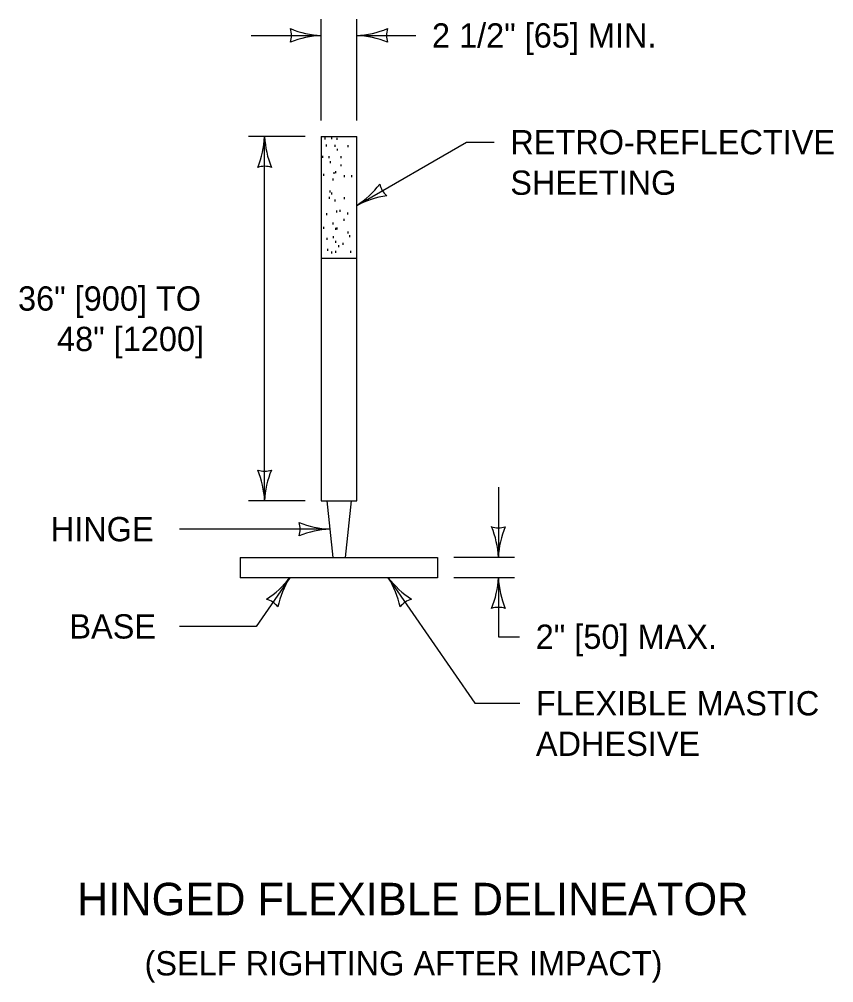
# Model space of a CAD drawing. Extents: x 49991.4 to 50024.6, y 49987.6 to 50011.4.
# Drawn here: x 50022.61 to 50024.622, y 49990.008 to 49992.389 of the extents above; entities that cross this region are included whole.
import ezdxf

# ---------------------------------------------------------------- set-up
doc = ezdxf.new("R2010")
doc.units = 0
for name, color, linetype in [('Level 1', 7, 'Continuous'), ('Level 2', 7, 'Continuous'), ('Level 3', 7, 'Continuous')]:
    doc.layers.add(name, color=color, linetype=linetype)

msp = doc.modelspace()

# ---------------------------------------------------------------- linework, layer by layer
at = {"layer": 'Level 1'}
for p, q in [((50023.356, 49992.0992), (50023.356, 49991.1992)), ((50023.356, 49992.0992), (50023.4435, 49992.0992)), ((50023.3656, 49992.0921), (50023.3656, 49992.097)), ((50023.3824, 49992.093), (50023.3824, 49992.0979)), ((50023.3949, 49992.0914), (50023.3949, 49992.0963)), ((50023.4435, 49991.1992), (50023.4435, 49992.0992)), ((50023.3691, 49992.0751), (50023.3691, 49992.08)), ((50023.3901, 49992.0738), (50023.3901, 49992.0786)), ((50023.396, 49992.0645), (50023.396, 49992.0694)), ((50023.4225, 49992.0734), (50023.4225, 49992.0782)), ((50023.3602, 49992.0466), (50023.3602, 49992.0515)), ((50023.3758, 49992.0461), (50023.3758, 49992.051)), ((50023.3786, 49992.0338), (50023.3786, 49992.0386)), ((50023.4049, 49992.0462), (50023.4049, 49992.0511)), ((50023.4049, 49992.0259), (50023.4049, 49992.0307)), ((50023.3622, 49992.0025), (50023.3622, 49992.0074)), ((50023.3854, 49991.9904), (50023.3854, 49991.9953)), ((50023.3879, 49992.0069), (50023.3879, 49992.0117)), ((50023.3921, 49992.0086), (50023.3921, 49992.0135)), ((50023.413, 49991.9987), (50023.413, 49992.0036)), ((50023.4313, 49991.9994), (50023.4313, 49992.0042)), ((50023.3759, 49991.9455), (50023.3759, 49991.9504)), ((50023.3778, 49991.9614), (50023.3778, 49991.9662)), ((50023.382, 49991.9564), (50023.382, 49991.9613)), ((50023.3901, 49991.9388), (50023.3901, 49991.9436)), ((50023.413, 49991.9444), (50023.413, 49991.9492)), ((50023.3697, 49991.9049), (50023.3697, 49991.9098)), ((50023.3946, 49991.9119), (50023.3946, 49991.9167)), ((50023.403, 49991.913), (50023.403, 49991.9179)), ((50023.4123, 49991.8909), (50023.4123, 49991.8957)), ((50023.4218, 49991.9071), (50023.4218, 49991.912)), ((50023.3622, 49991.871), (50023.3622, 49991.8759)), ((50023.3854, 49991.8818), (50023.3854, 49991.8866)), ((50023.3921, 49991.8689), (50023.3921, 49991.8738)), ((50023.3954, 49991.8699), (50023.3954, 49991.8747)), ((50023.3704, 49991.8445), (50023.3704, 49991.8494)), ((50023.3859, 49991.8481), (50023.3859, 49991.853)), ((50023.4225, 49991.8596), (50023.4225, 49991.8645)), ((50023.4265, 49991.8509), (50023.4265, 49991.8557)), ((50023.3921, 49991.837), (50023.3921, 49991.8419)), ((50023.3994, 49991.8257), (50023.3994, 49991.8306)), ((50023.4103, 49991.8319), (50023.4103, 49991.8367)), ((50023.3725, 49991.8166), (50023.3725, 49991.8215)), ((50023.3824, 49991.8101), (50023.3824, 49991.815)), ((50023.3921, 49991.8119), (50023.3921, 49991.8168)), ((50023.4293, 49991.8121), (50023.4293, 49991.817)), ((50023.356, 49991.7992), (50023.4435, 49991.7992)), ((50023.356, 49991.1992), (50023.4435, 49991.1992)), ((50023.3697, 49991.1992), (50023.3847, 49991.0593)), ((50023.4297, 49991.1992), (50023.4147, 49991.0593)), ((50023.156, 49991.0593), (50023.156, 49991.0093)), ((50023.156, 49991.0593), (50023.6435, 49991.0593)), ((50023.6435, 49991.0593), (50023.6435, 49991.0093)), ((50023.6435, 49991.0093), (50023.156, 49991.0093))]:
    msp.add_line(p, q, dxfattribs=at)
at = {"layer": 'Level 3'}
for p, q in [((50023.356, 49992.1392), (50023.356, 49992.3892)), ((50023.4435, 49992.1392), (50023.4435, 49992.3892)), ((50023.1825, 49992.3492), (50023.356, 49992.3492)), ((50023.4435, 49992.3492), (50023.5894, 49992.3492)), ((50023.316, 49992.0992), (50023.176, 49992.0992)), ((50023.216, 49991.1992), (50023.216, 49992.0992)), ((50023.7935, 49991.2327), (50023.7935, 49991.0593)), ((50023.316, 49991.1992), (50023.176, 49991.1992)), ((50023.3772, 49991.1292), (50023.006, 49991.1292)), ((50023.8335, 49991.0593), (50023.6835, 49991.0593)), ((50023.8335, 49991.0093), (50023.6835, 49991.0093)), ((50023.7351, 49990.6989), (50023.8462, 49990.6989))]:
    msp.add_line(p, q, dxfattribs=at)
for points in [[(50023.4435, 49991.9288), (50023.7148, 49992.0854), (50023.783, 49992.0854)], [(50023.2779, 49991.0093), (50023.1951, 49990.8889), (50023.006, 49990.8889)], [(50023.5216, 49991.0093), (50023.7351, 49990.6989), (50023.8462, 49990.6989)], [(50023.7935, 49991.0093), (50023.7935, 49990.8634), (50023.8457, 49990.8634)]]:
    msp.add_lwpolyline(points, dxfattribs=at)
for centre, radius, start, end in [((50023.3651, 49992.5713), 0.2223, 247.456, 267.6395), ((50023.2278, 49992.3492), 0.0548, 342.1388, 17.8612), ((50023.3675, 49992.1165), 0.233, 92.8273, 112.0772), ((50023.432, 49992.5819), 0.233, 272.8273, 292.0772), ((50023.4343, 49992.127), 0.2223, 67.456, 87.6395), ((50023.5717, 49992.3492), 0.0548, 162.1388, 197.8612), ((50022.9938, 49992.1083), 0.2223, 337.456, 357.6395), ((50023.4487, 49992.1107), 0.233, 182.8273, 202.0772), ((50023.216, 49991.971), 0.0548, 72.1388, 107.8612), ((50023.3156, 49992.1236), 0.233, 303.2811, 322.5309), ((50023.554, 49991.9938), 0.0548, 192.5926, 228.3149), ((50023.5482, 49991.7327), 0.2223, 97.9098, 118.0933), ((50023.216, 49991.3274), 0.0548, 252.1388, 287.8612), ((50022.9833, 49991.1877), 0.233, 2.8273, 22.0772), ((50023.4381, 49991.19), 0.2223, 157.456, 177.6395), ((50023.3863, 49991.3513), 0.2223, 247.456, 267.6395), ((50023.249, 49991.1292), 0.0548, 342.1388, 17.8612), ((50023.7935, 49991.1875), 0.0548, 252.1388, 287.8612), ((50023.5608, 49991.0478), 0.233, 2.8273, 22.0772), ((50024.0156, 49991.0501), 0.2223, 157.456, 177.6395), ((50023.3887, 49990.8965), 0.233, 92.8273, 112.0772), ((50023.1, 49991.1427), 0.2223, 302.9394, 323.1229), ((50023.4761, 49990.8869), 0.233, 148.3107, 167.5606), ((50023.3334, 49990.8909), 0.2223, 11.9771, 32.1606), ((50023.7068, 49991.1506), 0.233, 217.3484, 236.5982), ((50023.5713, 49991.0184), 0.2223, 337.456, 357.6395), ((50024.0262, 49991.0208), 0.233, 182.8273, 202.0772), ((50023.2052, 49990.9036), 0.0548, 37.6222, 73.3446), ((50023.5942, 49990.9036), 0.0548, 106.6599, 142.3822), ((50023.7935, 49990.8811), 0.0548, 72.1388, 107.8612)]:
    msp.add_arc(centre, radius, start, end, dxfattribs=at)

# ---------------------------------------------------------------- texts
at = {"layer": 'Level 2'}
for s, height, p in [('2 1/2" [65] MIN.', 0.06, (50023.6294, 49992.3192)), ('RETRO-REFLECTIVE ', 0.06, (50023.823, 49992.0554)), ('SHEETING', 0.06, (50023.823, 49991.9554)), ('36" [900] TO', 0.06, (50022.6068, 49991.6692)), ('48" [1200]', 0.06, (50022.7032, 49991.5692)), ('HINGE', 0.06, (50022.6876, 49991.0992)), ('BASE', 0.06, (50022.7337, 49990.8589)), ('2" [50] MAX.', 0.06, (50023.8857, 49990.8334)), ('FLEXIBLE MASTIC ', 0.06, (50023.8862, 49990.6689)), ('ADHESIVE', 0.06, (50023.8862, 49990.5689)), ('HINGED FLEXIBLE DELINEATOR', 0.08, (50022.7526, 49990.1753)), ('(SELF RIGHTING AFTER IMPACT)', 0.06, (50022.9194, 49990.0264))]:
    msp.add_text(s, height=height, dxfattribs=at).set_placement(p)

doc.saveas('drawing.dxf')
